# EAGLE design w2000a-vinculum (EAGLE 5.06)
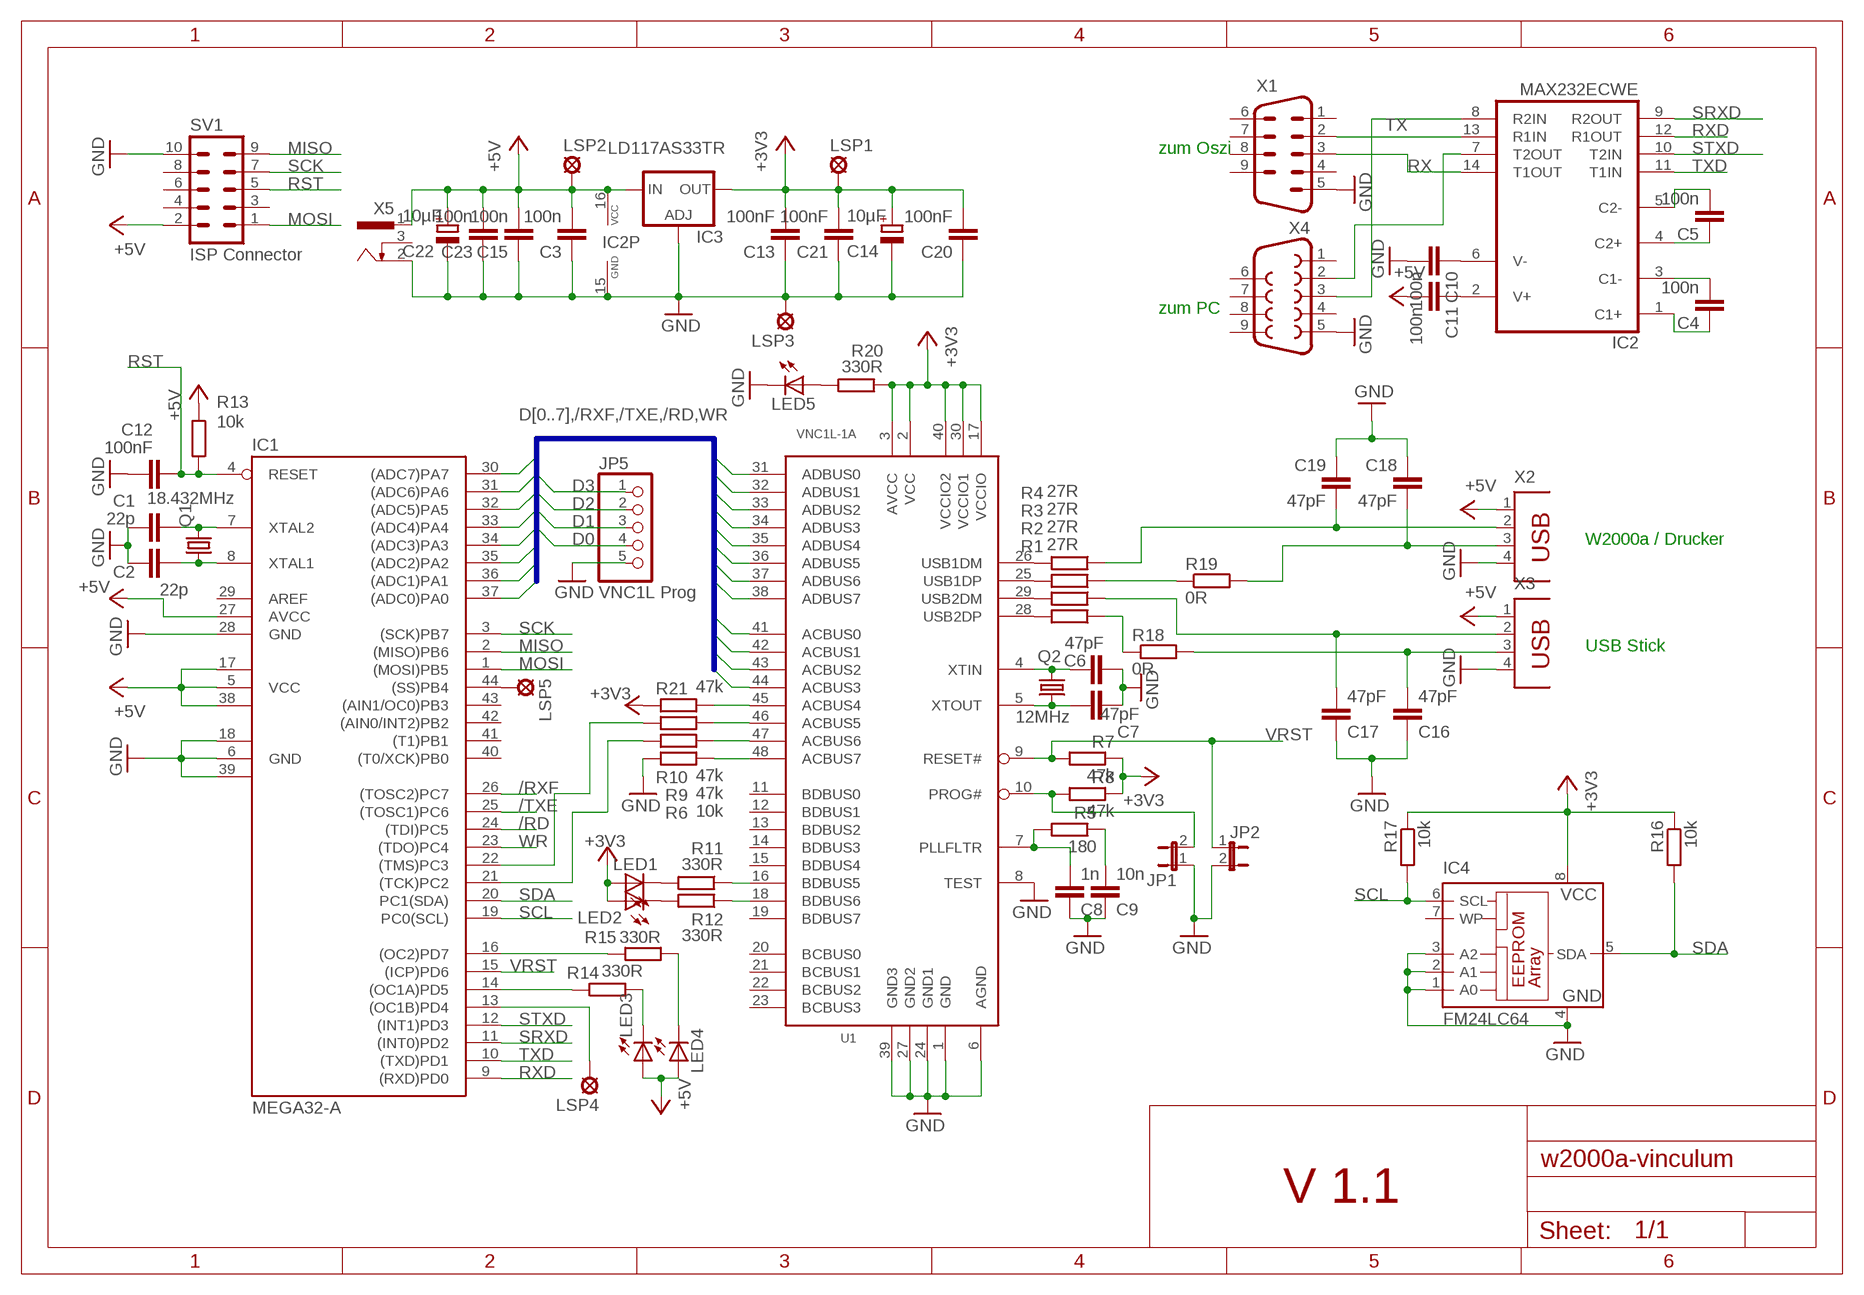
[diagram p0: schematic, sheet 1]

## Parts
C1  22p  C-EUC0603  [C0603]
C2  22p  C-EUC0603  [C0603]
C3  100n  C-EUC0603  [C0603]
C4  100n  C-EUC0603  [C0603]
C5  100n  C-EUC0603  [C0603]
C6  47pF  C-EUC0603  [C0603]
C7  47pF  C-EUC0603  [C0603]
C8  1n  C-EUC0603  [C0603]
C9  10n  C-EUC0603  [C0603]
C10  100n  C-EUC0603  [C0603]
C11  100n  C-EUC0603  [C0603]
C12  100nF  C-EUC0603  [C0603]
C13  100nF  C-EUC0603  [C0603]
C14  10µF  CPOL-EU153CLV-0505  [153CLV-0505]
C15  100n  C-EUC0603  [C0603]
C16  47pF  C-EUC0603  [C0603]
C17  47pF  C-EUC0603  [C0603]
C18  47pF  C-EUC0603  [C0603]
C19  47pF  C-EUC0603  [C0603]
C20  100nF  C-EUC0603  [C0603]
C21  100nF  C-EUC0603  [C0603]
C22  10µF  CPOL-EU153CLV-0405  [153CLV-0405]
C23  100n  C-EUC0603  [C0603]
IC1  MEGA32-A  [TQFP44]
IC2  MAX232ECWE  [SO16L]
IC3  LD117AS33TR  [SOT223]
IC4  FM24LC64  24C64SM  [SO-08M]
JP1  JP1E  [JP1]
JP2  JP1E  [JP1]
JP5  VNC1L Prog  PINHD-1X5  [1X05]
LED1  LEDCHIPLED_0603  [CHIPLED_0603]
LED2  LEDCHIPLED_0603  [CHIPLED_0603]
LED3  LEDCHIPLED_0603  [CHIPLED_0603]
LED4  LEDCHIPLED_0603  [CHIPLED_0603]
LED5  LEDCHIPLED_0603  [CHIPLED_0603]
LSP1  SE11  [SE11]
LSP2  SE11  [SE11]
LSP3  SE11  [SE11]
LSP4  SE11  [SE11]
LSP5  SE11  [SE11]
Q1  18.432MHz  CRYSTALHC49S  [HC49/S]
Q2  12MHz  CRYSTALHC49S  [HC49/S]
R1  27R  R-EU_R0603  [R0603]
R2  27R  R-EU_R0603  [R0603]
R3  27R  R-EU_R0603  [R0603]
R4  27R  R-EU_R0603  [R0603]
R5  180  R-EU_R0603  [R0603]
R6  10k  R-EU_R0603  [R0603]
R7  47k  R-EU_R0603  [R0603]
R8  47k  R-EU_R0603  [R0603]
R9  47k  R-EU_R0603  [R0603]
R10  47k  R-EU_R0603  [R0603]
R11  330R  R-EU_R0603  [R0603]
R12  330R  R-EU_R0603  [R0603]
R13  10k  R-EU_R0603  [R0603]
R14  330R  R-EU_R0603  [R0603]
R15  330R  R-EU_R0603  [R0603]
R16  10k  R-EU_R0603  [R0603]
R17  10k  R-EU_R0603  [R0603]
R18  0R  R-EU_R1206  [R1206]
R19  0R  R-EU_R1206  [R1206]
R20  330R  R-EU_R0603  [R0603]
R21  47k  R-EU_R0603  [R0603]
SV1  ISP Connector  ML10  [ML10]
U1  VNC1L-1A  [LQFP48]
X1  M09-182  [182-009-MALE]
X2  PN87520  [PN87520]
X3  PN87520  [PN87520]
X4  F09HP  [F09HP]
X5  733980-62  [733980-62]

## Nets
+3V3: C13.2 C14.+ C20.2 C21.2 IC3.4(OUT) IC4.8(VCC) LED1.A LED2.A LSP1.MP R7.1 R8.1 R16.1 R17.1 R20.1 R21.2 U1.2(VCC) U1.3(AVCC) U1.17(VCCIO) U1.30(VCCIO1) U1.40(VCCIO2)
+5V: C3.2 C11.2 C15.2 C22.+ C23.2 IC1.5(VCC) IC1.17(VCC1) IC1.27(AVCC) IC1.38(VCC2) IC2.16(VCC) IC3.3(IN) LED3.A LED4.A LSP2.MP R13.1 SV1.2 X2.1 X3.1 X5.1
/RD: IC1.24((TDI)PC5) U1.43(ACBUS2)
/RXF: IC1.26((TOSC2)PC7) U1.41(ACBUS0)
/TXE: IC1.25((TOSC1)PC6) U1.42(ACBUS1)
D0: IC1.37((ADC0)PA0) JP5.4 U1.31(ADBUS0)
D1: IC1.36((ADC1)PA1) JP5.3 U1.32(ADBUS1)
D2: IC1.35((ADC2)PA2) JP5.2 U1.33(ADBUS2)
D3: IC1.34((ADC3)PA3) JP5.1 U1.34(ADBUS3)
D4: IC1.33((ADC4)PA4) U1.35(ADBUS4)
D5: IC1.32((ADC5)PA5) U1.36(ADBUS5)
D6: IC1.31((ADC6)PA6) U1.37(ADBUS6)
D7: IC1.30((ADC7)PA7) U1.38(ADBUS7)
GND: C1.1 C2.1 C3.1 C6.1 C7.1 C8.1 C9.1 C10.2 C12.1 C13.1 C14.- C15.1 C16.1 C17.1 C18.1 C19.1 C20.1 C21.1 C22.- C23.1 IC1.6(GND) IC1.18(GND1) IC1.28(GND) IC1.39(GND2) IC2.15(GND) IC3.1(ADJ) IC4.1(A0) IC4.2(A1) IC4.3(A2) IC4.4(GND) JP1.1 JP2.2 JP5.5 LED5.C LSP3.MP R6.2 SV1.10 U1.1(GND) U1.6(AGND) U1.8(TEST) U1.24(GND1) U1.27(GND2) U1.39(GND3) X1.5 X2.4 X3.4 X4.5 X5.2
MISO: IC1.2((MISO)PB6) SV1.9
MOSI: IC1.1((MOSI)PB5) SV1.1
N$1: C1.2 IC1.7(XTAL2) Q1.2
N$2: C2.2 IC1.8(XTAL1) Q1.1
N$3: C4.1 IC2.1(C1+)
N$4: C4.2 IC2.3(C1-)
N$5: C5.1 IC2.4(C2+)
N$6: R4.2 U1.26(USB1DM)
N$7: R3.2 U1.25(USB1DP)
N$8: R2.2 U1.29(USB2DM)
N$9: R1.2 U1.28(USB2DP)
N$10: C6.2 Q2.2 U1.4(XTIN)
N$11: C7.2 Q2.1 U1.5(XTOUT)
N$12: C5.2 IC2.5(C2-)
N$13: C9.2 R5.1
N$14: C10.1 IC2.6(V-)
N$15: C8.2 R5.2 U1.7(PLLFLTR)
N$16: C11.1 IC2.2(V+)
N$17: R6.1 U1.48(ACBUS7)
N$18: LED4.C R15.1
N$19: JP1.2 R8.2 U1.10(PROG#)
N$20: R9.1 U1.47(ACBUS6)
N$21: R10.1 U1.46(ACBUS5)
N$22: R12.1 U1.18(BDBUS6)
N$23: R11.1 U1.16(BDBUS5)
N$26: IC2.7(T2OUT) X4.2
N$27: IC2.8(R2IN) X4.3
N$28: LED1.C R11.2
N$29: LED2.C R12.2
N$30: IC1.14((OC1A)PD5) R14.2
N$31: IC1.16((OC2)PD7) R15.2
N$32: LED3.C R14.1
N$33: C19.2 R4.1 X2.2
N$34: R21.1 U1.45(ACBUS4)
N$35: IC1.21((TCK)PC2) R9.2
N$36: IC1.22((TMS)PC3) R10.2
N$37: C18.2 R19.2 X2.3
N$38: C17.2 R2.1 X3.2
N$39: C16.2 R18.2 X3.3
N$41: R1.1 R18.1
N$43: IC1.13((OC1B)PD4) LSP4.MP
N$44: R3.1 R19.1
N$45: IC1.44((SS)PB4) LSP5.MP
N$46: LED5.A R20.2
RST: C12.2 IC1.4(RESET) R13.2 SV1.5
RX: IC2.14(T1OUT) X1.3
RXD: IC1.9((RXD)PD0) IC2.12(R1OUT)
SCK: IC1.3((SCK)PB7) SV1.7
SCL: IC1.19(PC0(SCL)) IC4.6(SCL) R17.2
SDA: IC1.20(PC1(SDA)) IC4.5(SDA) R16.2
SRXD: IC1.11((INT0)PD2) IC2.9(R2OUT)
STXD: IC1.12((INT1)PD3) IC2.10(T2IN)
TX: IC2.13(R1IN) X1.2
TXD: IC1.10((TXD)PD1) IC2.11(T1IN)
VRST: IC1.15((ICP)PD6) JP2.1 R7.2 U1.9(RESET#)
WR: IC1.23((TDO)PC4) U1.44(ACBUS3)
Unconnected: IC1.29(AREF) IC1.40((T0/XCK)PB0) IC1.41((T1)PB1) IC1.42((AIN0/INT2)PB2) IC1.43((AIN1/OC0)PB3) IC4.7(WP) SV1.3 SV1.4 SV1.6 SV1.8 U1.11(BDBUS0) U1.12(BDBUS1) U1.13(BDBUS2) U1.14(BDBUS3) U1.15(BDBUS4) U1.19(BDBUS7) U1.20(BCBUS0) U1.21(BCBUS1) U1.22(BCBUS2) U1.23(BCBUS3) X1.1 X1.4 X1.6 X1.7 X1.8 X1.9 X4.1 X4.4 X4.6 X4.7 X4.8 X4.9 X5.3

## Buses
D[0..7],/RXF,/TXE,/RD,WR

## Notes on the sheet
- zum Oszi
- zum PC
- W2000a / Drucker
- USB Stick
- V 1.1

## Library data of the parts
C1-C13 C15-C21 C23 = rcl:C-EU: CAPACITOR, European symbol
C14 C22 = rcl:CPOL-EU: POLARIZED CAPACITOR, European symbol
IC1 = atmel:MEGA32: MICROCONTROLLER 32 Kbytes FLASH 2 Kbytes SRAM 1 Kbytes EEPROM USART 8-channel 10 bit ADC Source: www.atmel.com .. doc2503.pdf
IC2 = maxim:MAX232ECWE: RS232 TRANSEIVER
IC3 = v-reg:LD117A?*: Low drop fixed and adjustable positive voltage regulators 1 A Source: http://www.st.com/stonline/products/literature/ds/7194/ld1117axx.pdf
IC4 = microchip:24*: Serial EEPROM I2C
JP1 JP2 = jumper:JP1E: JUMPER
JP5 = pinhead:PINHD-1X5: PIN HEADER
LED1-LED5 = led:LED: LED
LSP1-LSP5 = solpad:SE11: SOLDER PAD
Q1 Q2 = crystal:CRYSTAL: CRYSTAL
R1-R21 = rcl:R-EU_: RESISTOR, European symbol
SV1 = con-harting-ml:ML10: HARTING
U1 = ftdichip-1:VNC1L
X1 = con-subd:M09: SUB-D
X2 X3 = con-berg:PN87520: BERG USB connector
X4 = con-subd:F09: SUB-D
X5 = con-conrad:73398?: FEMALE PRINT CONNECTOR Niedervolt-Steckverbinder Distributor Conrad

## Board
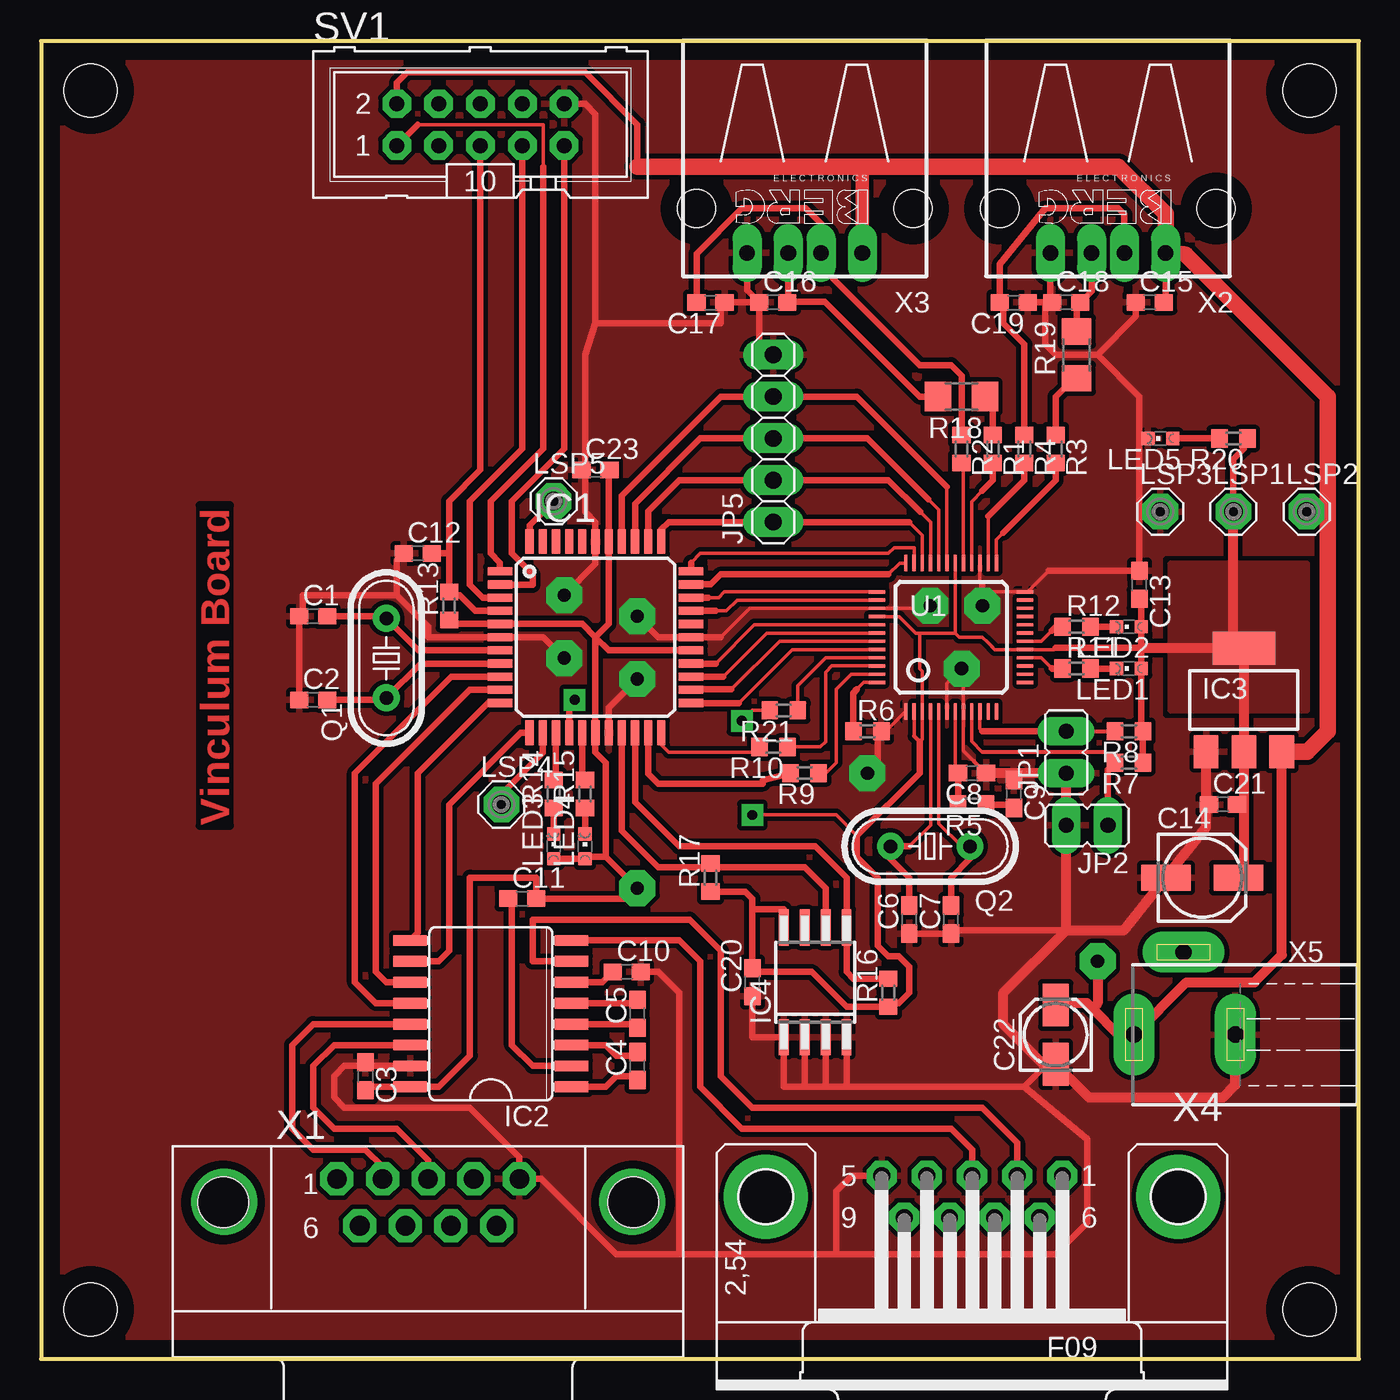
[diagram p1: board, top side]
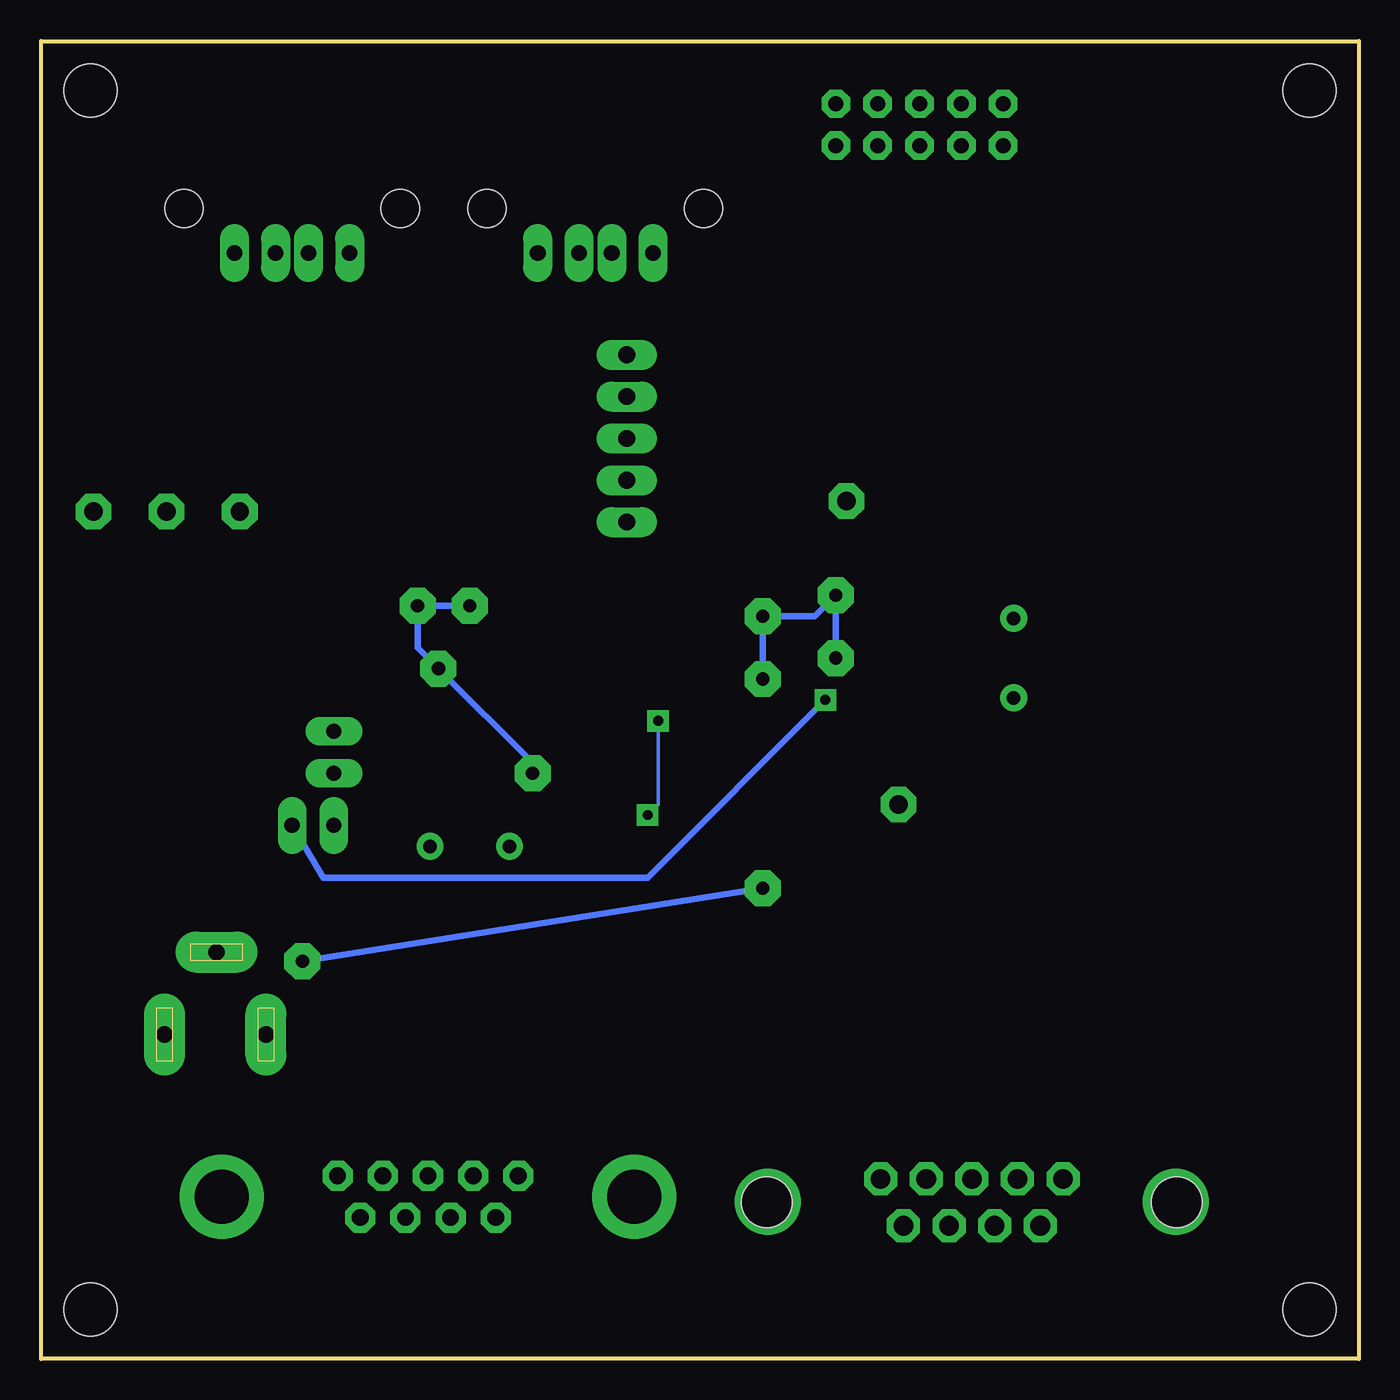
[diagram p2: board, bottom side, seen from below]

Size 80 x 80 mm. Coordinates in mm from the lower left corner, seen from the top.
Outline: 0,0 80,0 80,80 0,80 0,0
Copper layers (1*16): Top 0.035mm / dielectric 1.5mm / Bottom 0.035mm
Design rules "default *": minimum track width 0.2mm, minimum drill 31mil, track to track 11mil, track to pad 11mil, pad to pad 11mil, via to via 11mil, smd to smd 11mil, copper to edge 40mil, drill to drill 8mil, minimum pad ring 16mil, minimum via ring 14mil, stop-mask expansion 4mil, vias tented up to drill 0mil, thermal gap 10mil
Holes 3.2 mm at 3,77 77,77 3,3 77,3

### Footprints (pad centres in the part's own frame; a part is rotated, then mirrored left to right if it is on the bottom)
C0603 = smd 1.1 x 1: 1 -0.85,0; 2 0.85,0
153CLV-0505 = smd 3 x 1.6: + 2.2,0; - -2.2,0
153CLV-0405 = smd 2.6 x 1.6: + 1.8,0; - -1.8,0
TQFP44 = smd 1.5 x 0.5: 1 -5.8,4; 2 -5.8,3.2; 3 -5.8,2.4; 4 -5.8,1.6; 5 -5.8,0.8; 6 -5.8,0; 7 -5.8,-0.8; 8 -5.8,-1.6; 9 -5.8,-2.4; 10 -5.8,-3.2; 11 -5.8,-4; 23 5.8,-4; 24 5.8,-3.2; 25 5.8,-2.4; 26 5.8,-1.6; 27 5.8,-0.8; 28 5.8,0; 29 5.8,0.8; 30 5.8,1.6; 31 5.8,2.4; 32 5.8,3.2; 33 5.8,4 | smd 0.5 x 1.5: 12 -4,-5.8; 13 -3.2,-5.8; 14 -2.4,-5.8; 15 -1.6,-5.8; 16 -0.8,-5.8; 17 0,-5.8; 18 0.8,-5.8; 19 1.6,-5.8; 20 2.4,-5.8; 21 3.2,-5.8; 22 4,-5.8; 34 4,5.8; 35 3.2,5.8; 36 2.4,5.8; 37 1.6,5.8; 38 0.8,5.8; 39 0,5.8; 40 -0.8,5.8; 41 -1.6,5.8; 42 -2.4,5.8; 43 -3.2,5.8; 44 -4,5.8
SO16L = smd 0.66 x 2.032: 1 -4.445,-4.902; 2 -3.175,-4.902; 3 -1.905,-4.902; 4 -0.635,-4.902; 5 0.635,-4.902; 6 1.905,-4.902; 7 3.175,-4.902; 8 4.445,-4.902; 9 4.445,4.902; 10 3.175,4.902; 11 1.905,4.902; 12 0.635,4.902; 13 -0.635,4.902; 14 -1.905,4.902; 15 -3.175,4.902; 16 -4.445,4.902
SOT223 = smd 1.5 x 2: 1 -2.3,-3.15; 2 0,-3.15; 3 2.3,-3.15 | smd 3.8 x 2: 4 0,3.15
SO-08M = smd 0.6 x 2.2: 1 -1.905,-3.33; 2 -0.635,-3.33; 3 0.635,-3.33; 4 1.905,-3.33; 5 1.905,3.33; 6 0.635,3.33; 7 -0.635,3.33; 8 -1.905,3.33
JP1 = drill 0.914 long: 1 0,-1.27; 2 0,1.27
1X05 = drill 1.016 long: 1 -5.08,0; 2 -2.54,0; 3 0,0; 4 2.54,0; 5 5.08,0
CHIPLED_0603 = smd 0.8 x 0.8: A 0,-0.75; C 0,0.75
SE11 = drill 1.118 pad 2.159 octagon: MP 0,0
HC49/S = drill 0.813 round: 1 -2.413,0; 2 2.413,0
R0603 = smd 1 x 1.1: 1 -0.85,0; 2 0.85,0
R1206 = smd 1.6 x 1.803: 1 -1.422,0; 2 1.422,0
ML10 = drill 0.914 octagon: 1 -5.08,-1.27; 2 -5.08,1.27; 3 -2.54,-1.27; 4 -2.54,1.27; 5 0,-1.27; 6 0,1.27; 7 2.54,-1.27; 8 2.54,1.27; 9 5.08,-1.27; 10 5.08,1.27
LQFP48 = smd 0.2 x 1: 1 -2.75,-4.5; 2 -2.25,-4.5; 3 -1.75,-4.5; 4 -1.25,-4.5; 5 -0.75,-4.5; 6 -0.25,-4.5; 7 0.25,-4.5; 8 0.75,-4.5; 9 1.25,-4.5; 10 1.75,-4.5; 11 2.25,-4.5; 12 2.75,-4.5; 25 2.75,4.5; 26 2.25,4.5; 27 1.75,4.5; 28 1.25,4.5; 29 0.75,4.5; 30 0.25,4.5; 31 -0.25,4.5; 32 -0.75,4.5; 33 -1.25,4.5; 34 -1.75,4.5; 35 -2.25,4.5; 36 -2.75,4.5 | smd 1 x 0.2: 13 4.5,-2.75; 14 4.5,-2.25; 15 4.5,-1.75; 16 4.5,-1.25; 17 4.5,-0.75; 18 4.5,-0.25; 19 4.5,0.25; 20 4.5,0.75; 21 4.5,1.25; 22 4.5,1.75; 23 4.5,2.25; 24 4.5,2.75; 37 -4.5,2.75; 38 -4.5,2.25; 39 -4.5,1.75; 40 -4.5,1.25; 41 -4.5,0.75; 42 -4.5,0.25; 43 -4.5,-0.25; 44 -4.5,-0.75; 45 -4.5,-1.25; 46 -4.5,-1.75; 47 -4.5,-2.25; 48 -4.5,-2.75
182-009-MALE = drill 1.194 pad 1.524 octagon: 1 -5.537,10.923; 2 -2.769,10.923; 3 0,10.923; 4 2.769,10.923; 5 5.537,10.923; 6 -4.153,8.08; 7 -1.384,8.08; 8 1.384,8.08; 9 4.153,8.08 | hole 3.048: -12.446,9.501; 12.446,9.501
PN87520 = drill 0.95 long: 1 -3.5,2.71; 2 -1,2.71; 3 1,2.71; 4 3.5,2.71 | hole 2.3: -6.57,0; 6.57,0
F09HP = drill 1.016 octagon: 1 -5.486,-1.27; 2 -2.743,-1.27; 3 0,-1.27; 4 2.743,-1.27; 5 5.486,-1.27; 6 -4.115,1.27; 7 -1.372,1.27; 8 1.372,1.27; 9 4.115,1.27 | drill 3.302 pad 5.08 round: G1 -12.522,0; G2 12.522,0
733980-62 = drill 1 pad 2.5 long: 1 0,8.57; 2 0,2.42; 3 5,5.57

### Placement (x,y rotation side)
C1  16.51,45.09 0 top
C2  16.51,40.01 0 top
C3  19.68,17.14 270 top
C4  36.2,17.78 90 top
C5  36.2,20.95 90 top
C6  52.7,26.67 90 top
C7  55.24,26.67 90 top
C8  56.52,35.56 180 top
C9  59.05,34.29 270 top
C10  35.56,23.5 0 top
C11  29.21,27.94 0 top
C12  22.86,48.9 0 top
C13  66.67,46.99 270 top
C14  70.48,29.21 0 top
C15  67.31,64.14 0 top
C16  44.45,64.14 0 top
C17  40.64,64.14 180 top
C18  62.23,64.14 0 top
C19  59.05,64.14 180 top
C20  43.18,22.86 90 top
C21  71.75,33.66 0 top
C22  61.59,19.68 90 top
C23  33.66,53.98 0 top
IC1  33.66,43.81 0 top
IC2  27.3,20.95 90 top
IC3  73.03,40.01 0 top
IC4  46.99,22.86 0 top
JP1  62.23,36.83 0 top
JP2  63.5,32.38 90 top
JP5  44.45,55.88 90 top
LED1  66.04,41.91 90 top
LED2  66.04,44.45 90 top
LED3  31.11,31.11 0 top
LED4  33.02,31.11 0 top
LED5  67.94,55.88 90 top
LSP1  72.39,51.44 0 top
LSP2  76.83,51.44 0 top
LSP3  67.94,51.44 0 top
LSP4  27.94,33.66 0 top
LSP5  31.11,52.07 0 top
Q1  20.95,42.55 90 top
Q2  53.98,31.11 180 top
R1  57.78,55.24 270 top
R2  55.88,55.24 270 top
R3  61.59,55.24 270 top
R4  59.69,55.24 270 top
R5  56.52,33.66 180 top
R6  50.16,38.1 0 top
R7  66.04,36.2 180 top
R8  66.04,38.1 180 top
R9  46.35,35.56 180 top
R10  44.45,37.15 180 top
R11  62.87,41.91 0 top
R12  62.87,44.45 0 top
R13  24.77,45.72 90 top
R14  31.11,34.29 90 top
R15  33.02,34.29 90 top
R16  51.44,22.23 90 top
R17  40.64,29.21 90 top
R18  55.88,58.42 180 top
R19  62.87,60.96 90 top
R20  72.39,55.88 180 top
R21  45.09,39.37 180 top
SV1  26.67,74.93 0 top
U1  55.24,43.81 0 top
X1  23.5,0 0 top
X2  64.77,69.85 180 top
X3  46.35,69.85 180 top
X4  56.52,9.84 180 top
X5  74.93,19.68 90 top

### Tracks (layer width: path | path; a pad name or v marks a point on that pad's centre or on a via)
+3V3  (via drill 0.6)
  Top 0.21: 53.34,37.47 53.49,37.62 U1.3 53.49,41.76 53.34,41.91 53.34,44.06 | 52.99,37.81 U1.2 | 55.49,44.06 U1.30 | 61.59,43.18 61.48,43.06 U1.17 57.9,43.06 57.47,43.5 | U1.40 52.09,45.06 53.09,44.06 53.34,44.06 | 53.34,44.06 55.49,44.06 | 55.49,44.06 55.74,43.81 57.15,43.81 57.47,43.5 | 57.47,43.5 57.77,43.2 | R21.2 43.18,39.37 v42.55,38.73 | v43.18,33.02 48.26,33.02 49.53,31.75
  Top 0.254: 53.34,37.47 52.99,37.81
  Top 0.406: 43.18,27.3 C20.2 43.4,23.5 46.77,23.5 48.9,21.38 R16.1 51.65,21.59 52.07,21.59 52.7,22.23 52.7,23.81 52.07,24.45 51.44,24.45 50.8,25.08 50.8,29.21 49.53,30.48 49.53,31.75 53.34,35.56 53.34,37.47 | 43.18,27.3 45.09,27.3 IC4.8 | R7.1 R8.1 66.79,38.2 LED1.A 66.79,43.18 | 66.79,43.18 LED2.A 66.79,46.02 C13.2 | 61.59,43.18 66.79,43.18 | R17.1 42.76,28.36 43.18,27.94 43.18,27.3 | 73.03,29.5 C14.+ | 73.03,33.66 C21.2 | 73,43.18 IC3.4 | LSP1.MP 72.39,54.61 73.03,55.24 73.03,55.66 R20.1
  Top 0.61: 73.03,29.5 73.03,33.66 IC3.4 | 66.79,43.18 72.39,43.18 | 72.39,43.18 73,43.18 | 72.39,43.18 LSP1.MP
  Bottom 0.21: v42.55,38.73 42.55,33.66 v43.18,33.02
  pour Top (no thermals): 68.58,39.37 76.83,39.37 76.83,48.26 68.58,48.26
+5V  (via drill 0.8 pad 2.18)
  Top 0.406: 34.29,30.48 34.29,36.2 33.66,36.83 IC1.17 33.66,43.81 | 33.66,43.81 32.85,44.62 IC1.5 25.02,44.62 R13.1 | IC1.27 34.45,43.02 33.66,43.81 | 33.66,43.81 34.45,44.62 IC1.38 34.45,53.92 C23.2 | 50.16,72.39 49.85,72.08 | SV1.2 21.59,77.47 22.23,78.11 33.02,78.11 36.2,74.93 36.2,72.39 | X2.1 | X2.1 68.27,64.25 C15.2 | C3.2 19.68,16.51 IC2.16 24.13,16.51 26.04,18.41 26.04,29.21 30.06,29.21 C11.2 35.56,27.94 v36.2,28.57 34.29,30.48 | 61.7,21.59 C22.+ | LED3.A LED4.A 33.13,30.36 33.13,30.48 34.29,30.48
  Top 0.61: IC3.3 75.33,24.52 73.66,22.86 69.53,22.86 X5.1 65.41,19.68 63.82,21.27 | 63.82,21.27 63.5,21.59 61.7,21.59 | v64.14,24.13 64.14,21.59 63.82,21.27 | 78.11,51.44 LSP2.MP
  Top 0.813: X3.1 | 49.85,72.08 X3.1 | X2.1 69.39,67.14 69.5,67.02
  Top 1.016: 36.2,72.39 50.16,72.39 65.41,72.39 68.27,69.53 X2.1 | IC3.3 76.86,36.85 78.11,38.1 78.11,51.44 78.11,58.42 69.5,67.02
  Bottom 0.406: v36.2,28.57 v64.14,24.13
/RD
  Top 0.21: U1.43 44.84,43.56 41.91,40.64
  Top 0.406: 41.91,40.64 39.48,40.64 IC1.24
/RXF
  Top 0.21: U1.41 43.3,44.56 40.95,42.22
  Top 0.406: IC1.26 40.95,42.22
/TXE
  Top 0.21: U1.42 44.06,44.06 41.41,41.41
  Top 0.406: IC1.25 41.41,41.41
D0
  Top 0.21: 54.99,52.95 U1.31
  Top 0.406: IC1.37 35.26,52.4 41.27,58.42 JP5.4 49.53,58.42 54.99,52.95
D1
  Top 0.21: U1.32 54.49,51.55 53.86,52.19
  Top 0.406: IC1.36 36.05,51.93 40.01,55.88 JP5.3 50.16,55.88 53.86,52.19
D2
  Top 0.21: U1.33 53.99,50.78 53.36,51.41
  Top 0.406: IC1.35 36.85,51.46 38.73,53.34 JP5.2 51.44,53.34 53.36,51.41
D3
  Top 0.21: U1.34 53.49,50.01 52.7,50.8
  Top 0.406: IC1.34 37.66,50.35 38.1,50.8 JP5.1 52.7,50.8
D4
  Top 0.21: U1.35 52.99,49.24 51.78,49.24 51.44,48.9 40.01,48.9 39.45,48.34
  Top 0.406: IC1.33 39.45,48.34
D5
  Top 0.21: U1.36 52.12,48.31 51.44,47.62
  Top 0.406: IC1.32 40.66,47.02 41.27,47.62 51.44,47.62
D6
  Top 0.21: U1.37 41.48,46.56 41.13,46.22 40.5,46.22
  Top 0.406: IC1.31 40.5,46.22
D7
  Top 0.21: U1.38 42.26,46.06 41.6,45.41 40.97,45.41
  Top 0.406: IC1.30 40.97,45.41
GND  (via drill 0.8 pad 2.18)
  Top 0.21: 51.28,38.1 U1.1 | 41.27,43.81 43.02,45.56 U1.39 53.82,45.56 | 61.17,47.84 59.9,46.56 U1.24 57.36,46.56 57.15,46.35 | U1.27 56.99,47.15 57.15,46.99 | U1.6 54.99,41.02 v55.88,41.91 55.99,41.8 U1.8 55.99,36.93 56.63,36.3
  Top 0.254: C8.1 56.63,36.3 | v53.98,45.72 53.82,45.56
  Top 0.406: 38.73,6.35 34.92,6.35 30.35,10.92 X1.5 29.03,12.24 26.04,15.24 18.41,15.24 17.78,15.88 17.78,17.14 18.41,17.78 19.68,17.78 | 38.73,6.35 38.73,22.23 37.47,23.5 C10.2 | 38.73,6.35 48.26,6.35 | 48.9,16.51 IC4.4 | 46.35,16.51 45.09,16.51 IC4.1 43.18,19.53 C20.1 | 47.62,16.51 46.35,16.51 | 48.9,16.51 47.62,16.51 | 46.35,16.51 IC4.2 | 47.62,16.51 IC4.3 | 59.69,16.51 63.5,13.34 63.5,8.26 61.59,6.35 48.26,6.35 | 59.69,16.51 48.9,16.51 | C2.1 C1.1 15.88,45.3 15.88,46.35 21.59,46.35 | C6.1 C7.1 55.46,26.04 62.23,26.04 | 51.28,38.1 R6.2 50.8,38.1 50.8,36.2 v50.16,35.56 | 41.27,43.81 IC1.28 37.47,43.81 v36.2,45.09 | JP1.1 JP2.2 | 61.17,47.84 C13.1 66.67,51.44 | 60.96,64.14 C19.1 | C16.1 C17.1 41.27,63.92 41.27,62.87 33.66,62.87 | SV1.10 33.02,76.2 33.66,75.56 33.66,62.87 | 33.02,53.98 33.02,51.44 33.66,50.8 IC1.39 33.66,48.26 v31.75,46.35 | 33.02,53.98 33.02,60.96 33.66,62.87 | v31.75,42.55 30.48,43.81 IC1.6 23.5,43.81 23.5,44.45 21.59,46.35 | IC1.18 34.45,39.53 v36.2,41.27 | v57.15,45.72 57.15,46.35 57.15,46.99 | 60.96,64.14 C18.1 61.27,64.25 X2.4 | 60.96,64.14 60.96,61.59 61.59,60.96 64.14,60.96 | 64.14,60.96 66.67,58.42 66.67,55.88 | 48.26,6.35 48.26,10.16 49.21,11.11 X4.5 | 21.59,46.35 21.59,48.48 C12.1 | C16.1 42.85,64.88 | JP5.5 43.6,61.81 C16.1 | X2.4 | 42.85,64.88 X3.4 | 42.85,64.88 | C15.1 66.46,63.28 64.14,60.96 | 66.67,51.44 66.67,55.88 | 19.68,17.78 IC2.15 | 19.68,17.78 C3.1 | C22.- 61.06,17.89 59.69,16.51 | 70.72,33.66 C21.1 | 66.67,51.44 LSP3.MP | 33.02,53.98 C23.1 | 66.67,55.88 LED5.C
  Top 0.61: 62.23,26.04 JP1.1 59.48,35.56 C9.1 59.27,35.56 C8.1 | X5.2 72.51,16.63 71.75,15.88 63.6,15.88 C22.- 60.85,17.89 58.42,20.32 58.42,22.23 62.23,26.04 | IC3.1 70.72,33.66 70.72,32.28 C14.- 65.75,26.04 62.23,26.04
  Bottom 0.406: v53.98,45.72 v57.15,45.72 57.15,43.18 v55.88,41.91 50.16,36.2 v50.16,35.56 | v36.2,41.27 v36.2,45.09 33.02,45.09 v31.75,46.35 v31.75,42.55
  pour Top (rank 2): 0,80.01 80.01,80.01 80.01,0 0,0
MISO
  Top 0.406: SV1.9 31.75,55.24 28.57,52.07 28.57,48.9 29.84,47.62 29.84,46.99 27.88,46.99 IC1.2
MOSI
  Top 0.21: 22.86,74.93 30.48,74.93 30.48,72.39
  Top 0.406: 22.86,74.93 SV1.1 | 30.48,72.39 30.48,55.24 27.3,52.07 27.3,48.9 27.86,48.34 IC1.1
N$1
  Top 0.406: IC1.7 22.9,43.02 Q1.2 20.83,45.09 C1.2
N$2
  Top 0.406: IC1.8 23.04,42.22 Q1.1 20.83,40.01 C2.2
N$3
  Top 0.406: IC2.1 34.29,16.51 34.92,17.14 35.98,17.14 C4.1
N$4
  Top 0.406: IC2.3 34.29,19.05 34.92,18.41 35.98,18.41 C4.2
N$5
  Top 0.406: C5.1 36.2,20.32 IC2.4
N$6
  Top 0.21: U1.26 57.49,51.15
  Top 0.406: 57.49,51.15 59.69,53.34 R4.2
N$7
  Top 0.21: U1.25 57.99,49.74 58.42,50.16
  Top 0.406: R3.2 61.59,53.34 58.42,50.16
N$8
  Top 0.21: U1.29 55.99,54.28
  Top 0.406: 55.99,54.28 R2.2
N$9
  Top 0.21: U1.28 56.49,52.05 57.15,52.7
  Top 0.406: R1.2 57.78,53.34 57.15,52.7
N$10
  Top 0.21: U1.4 53.99,32.41 52.7,31.11
  Top 0.406: 52.7,31.11 Q2.2 51.56,30.35 52.7,29.21 C6.2
N$11
  Top 0.21: U1.5 54.49,32.5 55.88,31.11
  Top 0.406: 55.88,31.11 Q2.1 56.39,30.35 55.24,29.21 C7.2
N$12
  Top 0.406: C5.2 36.2,21.59 IC2.5
N$13
  Top 0.406: R5.1 59.05,33.66 C9.2
N$14
  Top 0.406: IC2.6 34.08,22.86 C10.1
N$15
  Top 0.21: 55.49,35.73 U1.7
  Top 0.406: 55.49,35.73 C8.2 R5.2
N$16
  Top 0.406: IC2.2 29.84,17.78 28.57,19.05 28.57,27.73 C11.1
N$17
  Top 0.2: 49.53,40.64 49.95,41.06
  Top 0.21: 49.95,41.06 U1.48
  Top 0.406: R6.1 49.31,40.42 49.53,40.64
N$18
  Top 0.406: LED4.C R15.1
N$19
  Top 0.2: 56.99,38.26 57.15,38.1
  Top 0.21: U1.10 56.99,38.26
  Top 0.254: 63.5,38.1 R8.2
  Top 0.406: 57.15,38.1 JP1.2 63.5,38.1
N$20
  Top 0.21: U1.47 49.19,41.56 48.26,40.64 48.26,36.2 47.62,35.56 R9.1
N$21
  Top 0.21: U1.46 47.99,42.06 47.62,41.7 47.62,37.47 47.31,37.15 R10.1
N$22
  Top 0.21: U1.18 60.71,43.56 61.34,44.2
  Top 0.406: 61.34,44.2 61.59,44.45 R12.1
N$23
  Top 0.21: U1.16 60.73,42.56 61.36,41.93
  Top 0.406: 61.36,41.93 61.38,41.91 R11.1
N$24  (via drill 0.6 pad 4)
  other vias: 35.88,9.53
N$25  (via drill 0.6 pad 4)
  other vias: 11.11,9.53
N$26
  Top 0.406: IC2.7 29.84,24.13 29.84,26.67 39.37,26.67 41.27,24.77 41.27,17.14 43.18,15.24 57.15,15.24 59.26,13.13 X4.2
N$27
  Top 0.406: IC2.8 38.73,25.4 40.01,24.13 40.01,16.51 42.55,13.97 55.24,13.97 56.52,12.7 X4.3
N$28
  Top 0.406: LED1.C R11.2
N$29
  Top 0.406: LED2.C R12.2
N$30
  Top 0.406: IC1.14 31.25,35.28 R14.2
N$31
  Top 0.406: IC1.16 32.85,35.3 R15.2
N$32
  Top 0.406: LED3.C R14.1
N$33
  Top 0.406: R4.1 59.69,61.59 58.42,62.87 58.42,63.92 C19.2 58.2,66.46 60.96,69.85 65.41,69.85 65.77,69.48 X2.2
N$34
  Top 0.21: U1.45 47.65,42.56 45.94,40.85 R21.1 46.35,39.79
N$35
  Top 0.406: R9.2 43.81,35.14 43.81,34.92 37.47,34.92 36.85,35.53 IC1.21
N$36
  Top 0.21: R10.2 43.28,36.83 38.1,36.83 37.66,37.27 IC1.22
N$37
  Top 0.406: R19.2 62.87,63.92 C18.2 63.77,64.83 X2.3
N$38
  Top 0.406: R2.1 55.88,59.69 55.24,60.33 53.34,60.33 47.35,66.31 X3.2 47.35,68.92 46.43,69.85 42.55,69.85 39.79,67.09 C17.2
N$39
  Top 0.406: 45.35,64.19 X3.3 | C16.2 45.35,64.19 | R18.2 53.34,58.42 47.57,64.19 45.35,64.19
N$40  (via drill 0.6 pad 4)
  other vias: 44.13,9.84
N$41
  Top 0.406: R1.1 57.78,57.94 R18.1
N$42  (via drill 0.6 pad 4)
  other vias: 68.9,9.84
N$43
  Top 0.406: IC1.13 30.45,36.8 27.94,34.29 LSP4.MP
N$44
  Top 0.406: R3.1 61.59,58.42 62.55,59.37 | 62.55,59.37 62.87,59.69 | R19.1 62.7,59.37 62.55,59.37
N$45
  Top 0.406: IC1.44 29.66,50.61 LSP5.MP
N$46
  Top 0.406: LED5.A R20.2
RST
  Top 0.406: IC1.4 26.34,45.41 25.4,46.35 24.98,46.35 R13.2 24.77,48.9 | 24.77,48.9 C12.2 | SV1.5 26.67,53.98 24.77,52.07 24.77,48.9
RX
  Top 0.406: IC2.14 17.78,19.05 16.51,17.78 16.51,15.24 17.78,13.97 21.59,13.97 23.5,12.06 X1.3
RXD
  Top 0.406: IC1.9 24.91,41.41 19.05,35.56 19.05,22.86 20.32,21.59 IC2.12
SCK
  Top 0.406: SV1.7 29.21,55.24 26.04,52.07 26.04,46.99 26.81,46.22 IC1.3
SCL
  Top 0.406: IC4.6 47.62,28.57 46.35,29.84 40.64,29.84 | 40.64,29.84 37.47,29.84 35.26,32.05 IC1.19 | 40.64,29.84 R17.2
SDA
  Top 0.406: IC1.20 36.05,33.8 38.73,31.11 46.99,31.11 48.9,29.21 IC4.5 48.9,23.5 49.31,23.07 R16.2
SRXD
  Top 0.406: IC2.9 22.86,25.86 22.86,35.56 27.11,39.81 IC1.11
STXD
  Top 0.406: IC1.12 29.12,38.02 24.77,33.66 24.77,24.77 24.13,24.13 IC2.10
TX
  Top 0.406: IC2.13 16.51,20.32 15.24,19.05 15.24,13.97 16.51,12.7 19.68,12.7 20.73,11.66 X1.2
TXD
  Top 0.406: IC1.10 26.01,40.62 20.32,34.92 20.32,23.5 20.95,22.86 IC2.11
VRST  (via drill 0.6)
  Top 0.21: U1.9 56.49,37.48 57.15,36.83 | R7.2 64.56,36.83
  Top 0.254: 64.56,36.83 57.15,36.83
  Top 0.406: 65.41,35.98 R7.2 64.77,35.77 JP2.1 | IC1.15 32.05,39.67 v32.38,40.01
  Bottom 0.406: v32.38,40.01 43.18,29.21 62.87,29.21 JP2.1
WR
  Top 0.21: U1.44 45.6,43.06 42.35,39.81
  Top 0.406: IC1.23 42.35,39.81

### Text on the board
Top: Vinculum Board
